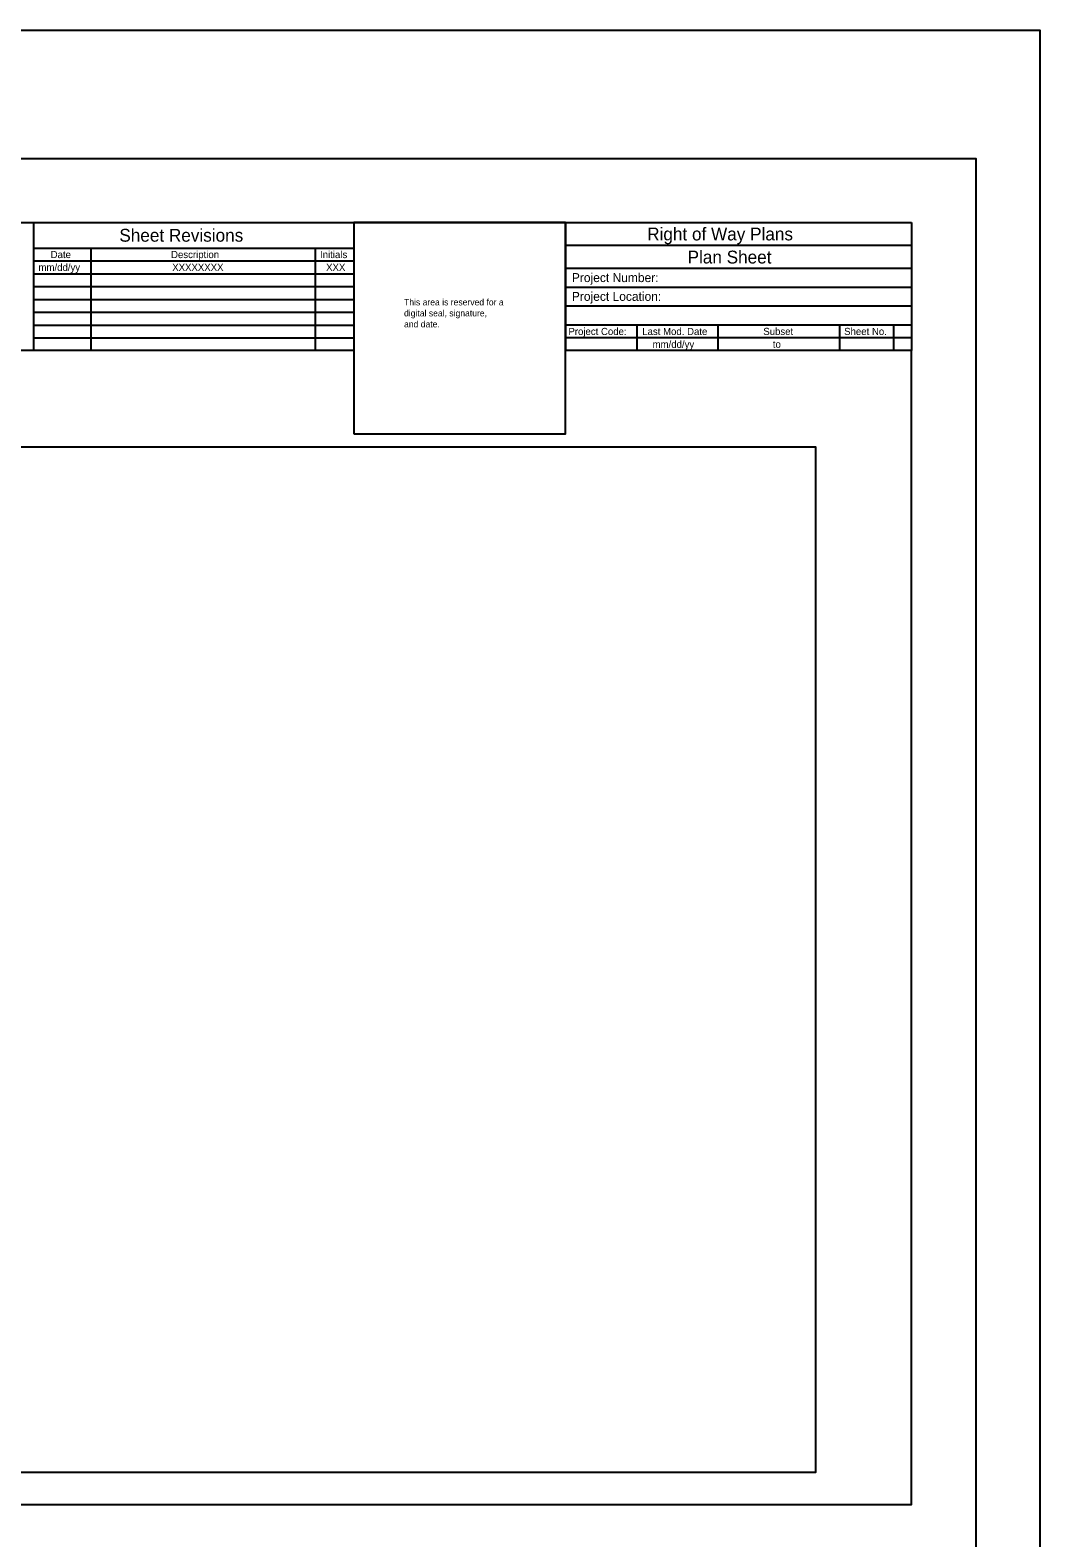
# Model space of a CAD drawing. Extents: x 0 to 3, y 0 to 2.
# Drawn here: x 2.344 to 3, y 1.02 to 2 of the extents above; entities that cross this region are included whole.
import ezdxf

# ---------------------------------------------------------------- set-up
doc = ezdxf.new("R2010")
doc.units = 0
for name, color, linetype in [('DRAFT_Information-No Plot', 7, 'Continuous'), ('SHEET_Lines', 7, 'Continuous'), ('SHEET_North Arrow', 7, 'Continuous'), ('SHEET_Plot Boundary', 7, 'Continuous'), ('SHEET_Text-Border Info', 7, 'Continuous')]:
    doc.layers.add(name, color=color, linetype=linetype)

msp = doc.modelspace()

# ---------------------------------------------------------------- linework, layer by layer
at = {"layer": 'DRAFT_Information-No Plot'}
msp.add_lwpolyline([(1.6875, 1.72917), (2.85417, 1.72917), (2.85417, 1.0625), (1.6875, 1.0625)], close=True, dxfattribs=at)
at = {"layer": 'SHEET_Lines'}
for p, q in [((1.625, 1.875), (2.91667, 1.875)), ((2.34583, 1.875), (2.34583, 1.79167)), ((2.55417, 1.875), (2.55417, 1.79167)), ((2.69167, 1.875), (2.69167, 1.79167)), ((2.91667, 1.875), (2.91667, 1.79167)), ((2.34583, 1.85833), (2.55417, 1.85833)), ((2.38333, 1.79167), (2.38333, 1.85833)), ((2.52917, 1.79167), (2.52917, 1.85833)), ((2.91667, 1.86), (2.69167, 1.86)), ((2.34583, 1.85), (2.55417, 1.85)), ((2.91667, 1.845), (2.69167, 1.845)), ((2.34583, 1.84167), (2.55417, 1.84167)), ((2.34583, 1.83333), (2.55417, 1.83333)), ((2.91667, 1.83278), (2.69167, 1.83278)), ((2.34583, 1.825), (2.55417, 1.825)), ((2.34583, 1.81667), (2.55417, 1.81667)), ((2.91667, 1.82056), (2.69167, 1.82056)), ((2.34583, 1.80833), (2.55417, 1.80833)), ((2.91667, 1.80833), (2.69167, 1.80833)), ((2.73833, 1.79167), (2.73833, 1.80833)), ((2.79083, 1.79167), (2.79083, 1.80833)), ((2.87, 1.79167), (2.87, 1.80833)), ((2.905, 1.79167), (2.905, 1.80833)), ((2.34583, 1.8), (2.55417, 1.8)), ((2.91667, 1.8), (2.69167, 1.8))]:
    msp.add_line(p, q, dxfattribs=at)
for points in [[(2.95833, 0.08333), (0.125, 0.08333), (0.125, 1.91667), (2.95833, 1.91667)], [(2.55417, 1.7375), (2.69167, 1.7375), (2.69167, 1.875), (2.55417, 1.875)]]:
    msp.add_lwpolyline(points, close=True, dxfattribs=at)
msp.add_lwpolyline([(2.55417, 1.79167), (1.625, 1.79167), (1.625, 1.04167), (2.91667, 1.04167), (2.91667, 1.79167), (2.69167, 1.79167)], dxfattribs=at)
at = {"layer": 'SHEET_Plot Boundary'}
msp.add_lwpolyline([(0, 2), (3, 2), (3, 0), (0, 0)], close=True, dxfattribs=at)

# ---------------------------------------------------------------- texts
at = {"layer": 'DRAFT_Information-No Plot'}
for s, height, p in [('This area is reserved for a', 0.0041667, (2.58677, 1.82108)), ('digital seal, signature,', 0.0041667, (2.58677, 1.81394)), ('and date.', 0.004167, (2.58677, 1.80679))]:
    msp.add_text(s, height=height, dxfattribs=at).set_placement(p)
at = {"layer": 'SHEET_North Arrow'}
for s, height, p in [('Right of Way Plans', 0.0083333, (2.74479, 1.86333)), ('Sheet Revisions', 0.0083333, (2.40172, 1.8625)), ('Plan Sheet', 0.008333, (2.77105, 1.84833))]:
    msp.add_text(s, height=height, dxfattribs=at).set_placement(p)
at = {"layer": 'SHEET_Text-Border Info'}
for s, height, p in [('Date', 0.004667, (2.35707, 1.85183)), ('Description', 0.0046667, (2.43532, 1.85183)), ('Initials', 0.004667, (2.53215, 1.85183)), ('mm/dd/yy', 0.004667, (2.34917, 1.8435)), ('XXXXXXXX', 0.004667, (2.43611, 1.8435)), ('XXX', 0.004667, (2.53611, 1.8435)), ('Project Number:', 0.0058333, (2.69583, 1.83625)), ('Project Location:', 0.0058333, (2.69583, 1.82403)), ('Project Code:', 0.0046667, (2.6936, 1.80183)), ('Last Mod. Date', 0.0046667, (2.74157, 1.80183)), ('Subset', 0.004667, (2.82026, 1.80183)), ('Sheet No.', 0.004667, (2.87282, 1.80183)), ('mm/dd/yy', 0.004667, (2.74831, 1.7935)), (' to ', 0.004667, (2.82473, 1.7935))]:
    msp.add_text(s, height=height, dxfattribs=at).set_placement(p)

doc.saveas('drawing.dxf')
